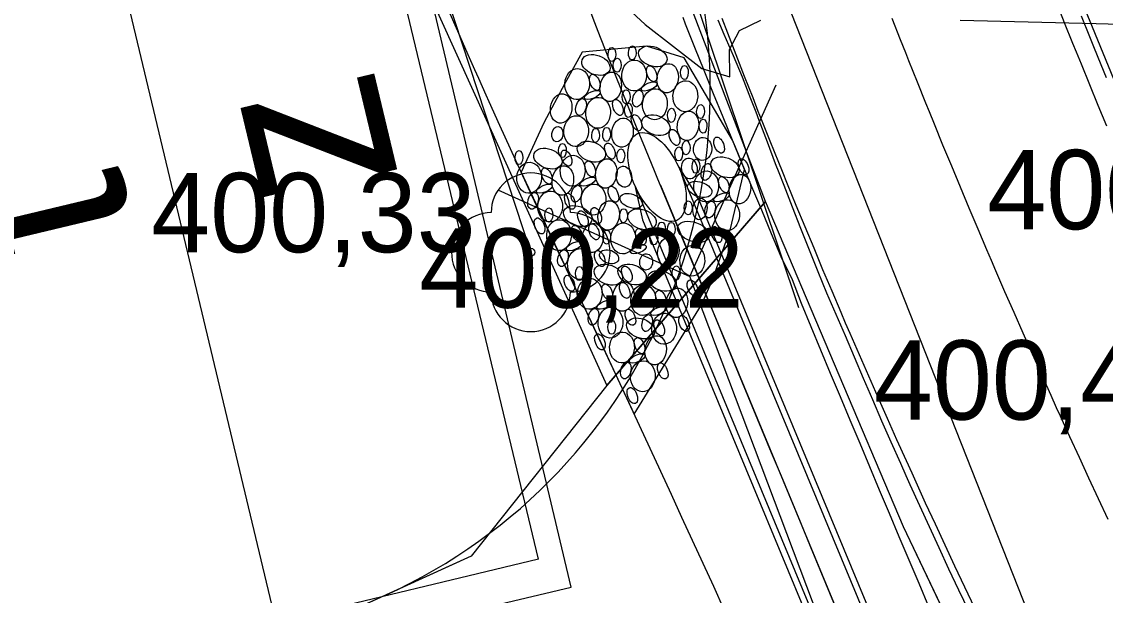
# Model space of a CAD drawing. Extents: x -574342 to -507939, y -1144044 to -1123894.
# Drawn here: x -508545.62 to -508531.96, y -1143255.8 to -1143248.56 of the extents above; entities that cross this region are included whole.
import ezdxf

# ---------------------------------------------------------------- set-up
doc = ezdxf.new("R2010")
doc.units = 0
for name, color, linetype in [('01_PARCELY_NAVRH_PC', 7, 'Continuous'), ('01_PARCELY_NAVRH_VHO', 7, 'Continuous'), ('01_PARCELY_NAVRH_ŽP', 7, 'Continuous'), ('04_ZPF_TECH_OPATŘEN_STAV', 7, 'Continuous'), ('1000', 7, 'Continuous'), ('21', 7, 'Continuous'), ('37', 7, 'Continuous'), ('54', 7, 'Continuous'), ('55', 7, 'Continuous'), ('62', 7, 'Continuous'), ('cesty', 7, 'Continuous'), ('Level 255', 7, 'Continuous'), ('propustek', 7, 'Continuous'), ('SO 101_popis oblouku', 7, 'Continuous'), ('VRST HL', 7, 'Continuous')]:
    doc.layers.add(name, color=color, linetype=linetype)

msp = doc.modelspace()

# ---------------------------------------------------------------- linework, layer by layer
msp.add_lwpolyline([(-508538.692, -1143255.691), (-508544.119, -1143232.805), (-508565.304, -1143237.829), (-508559.878, -1143260.714)], close=True)
at = {"layer": '01_PARCELY_NAVRH_PC'}
for points in [[(-508524.61, -1143277.77), (-508531.94, -1143260.32), (-508534.5, -1143254.93), (-508536.24, -1143250.83), (-508539.07, -1143243.44), (-508539.77, -1143241.25), (-508540.55, -1143238.43), (-508542.83, -1143228.38), (-508544.32, -1143217.47), (-508545.45, -1143205.07), (-508545.52, -1143198.58), (-508545.24, -1143191.32), (-508544.97, -1143188.3), (-508544.25, -1143181.83), (-508541.94, -1143173.53), (-508537.18, -1143176.51), (-508538.65, -1143182.46), (-508540.32, -1143193.28), (-508540.02, -1143209.35), (-508538.46, -1143221.35), (-508537.02, -1143231.11), (-508535.34, -1143238.37), (-508531.16, -1143250.06), (-508524.26, -1143263.08)], [(-508524.61, -1143277.77), (-508531.94, -1143260.32), (-508534.5, -1143254.93), (-508536.24, -1143250.83), (-508539.07, -1143243.44), (-508539.77, -1143241.25), (-508540.55, -1143238.43), (-508542.83, -1143228.38), (-508544.32, -1143217.47), (-508545.45, -1143205.07), (-508545.52, -1143198.58), (-508545.24, -1143191.32), (-508544.97, -1143188.3), (-508544.25, -1143181.83), (-508541.94, -1143173.53), (-508537.18, -1143176.51), (-508538.65, -1143182.46), (-508540.32, -1143193.28), (-508540.02, -1143209.35), (-508538.46, -1143221.35), (-508537.02, -1143231.11), (-508535.34, -1143238.37), (-508531.16, -1143250.06), (-508524.26, -1143263.08)], [(-508866.763, -1143529.283), (-508859.41, -1143516.97), (-508810.66, -1143431.99), (-508773.29, -1143386.75), (-508766.4, -1143380.31), (-508664.99, -1143316.89), (-508539, -1143259.35), (-508535.36, -1143259.89), (-508531.94, -1143260.32), (-508534.5, -1143254.93), (-508536.24, -1143250.83), (-508538.24, -1143253.15), (-508539.95, -1143255.3), (-508667.19, -1143313.15), (-508770.98, -1143377.64), (-508813.09, -1143427.79), (-508861.39, -1143510.97), (-508866.763, -1143520.059)]]:
    msp.add_lwpolyline(points, dxfattribs=at)
at = {"layer": '01_PARCELY_NAVRH_VHO'}
msp.add_lwpolyline([(-508536.24, -1143250.83), (-508539.07, -1143243.44), (-508539.77, -1143241.25), (-508540.55, -1143238.43), (-508542.83, -1143228.38), (-508544.32, -1143217.47), (-508545.45, -1143205.07), (-508545.52, -1143198.58), (-508545.24, -1143191.32), (-508544.97, -1143188.3), (-508544.25, -1143181.83), (-508551.68, -1143170.14), (-508558.5, -1143170.32), (-508555.03, -1143173.64), (-508548.66, -1143186.8), (-508549.63, -1143198.15), (-508549.79, -1143203.71), (-508547.53, -1143223.9), (-508542.99, -1143242.68), (-508538.24, -1143253.15)], close=True, dxfattribs=at)
at = {"layer": '01_PARCELY_NAVRH_ŽP'}
msp.add_lwpolyline([(-508555.03, -1143173.64), (-508548.66, -1143186.8), (-508549.63, -1143198.15), (-508549.79, -1143203.71), (-508547.53, -1143223.9), (-508542.99, -1143242.68), (-508538.24, -1143253.15), (-508539.95, -1143255.3), (-508547.25, -1143258.62), (-508651.11, -1143191.46), (-508662.59, -1143152.85), (-508637.59, -1143153.08), (-508621.09, -1143158.13), (-508610.87, -1143164.96), (-508585.59, -1143176.01), (-508569.25, -1143175.97)], close=True, dxfattribs=at)
at = {"layer": '04_ZPF_TECH_OPATŘEN_STAV'}
for points in [[(-508539.614, -1143250.685), (-508537.197, -1143251.776), (-508536.106, -1143249.359)], [(-508534.989, -1143257.623), (-508537.197, -1143251.776)]]:
    msp.add_lwpolyline(points, dxfattribs=at)
at = {"layer": '1000'}
for points in [[(-508532.579, -1143248.315), (-508532.475, -1143248.575), (-508532.37, -1143248.836), (-508532.326, -1143248.943), (-508532.264, -1143249.096), (-508532.158, -1143249.356), (-508532.051, -1143249.615), (-508531.943, -1143249.875)], [(-508536.762, -1143255.976), (-508536.894, -1143255.685), (-508537.027, -1143255.395), (-508537.16, -1143255.105), (-508537.294, -1143254.814), (-508537.427, -1143254.524), (-508537.561, -1143254.234), (-508537.695, -1143253.945), (-508537.83, -1143253.655), (-508537.964, -1143253.365), (-508538.099, -1143253.075), (-508538.234, -1143252.786), (-508538.369, -1143252.496), (-508538.504, -1143252.207), (-508538.64, -1143251.918), (-508538.776, -1143251.629), (-508538.912, -1143251.34), (-508539.008, -1143251.136), (-508539.048, -1143251.049), (-508539.185, -1143250.755), (-508539.321, -1143250.461), (-508539.457, -1143250.166), (-508539.591, -1143249.871), (-508539.724, -1143249.575), (-508539.762, -1143249.492), (-508539.857, -1143249.278), (-508539.906, -1143249.169), (-508539.989, -1143248.982), (-508540.12, -1143248.685), (-508540.25, -1143248.387)], [(-508532.264, -1143248.491), (-508532.158, -1143248.75), (-508532.115, -1143248.857), (-508532.052, -1143249.01), (-508531.946, -1143249.269)], [(-508534.181, -1143255.94), (-508534.306, -1143255.646), (-508534.43, -1143255.353), (-508534.555, -1143255.059), (-508534.679, -1143254.765), (-508534.803, -1143254.471), (-508534.927, -1143254.177), (-508535.05, -1143253.882), (-508535.174, -1143253.588), (-508535.297, -1143253.294), (-508535.42, -1143252.999), (-508535.543, -1143252.705), (-508535.665, -1143252.41), (-508535.787, -1143252.115), (-508535.902, -1143251.817), (-508536.043, -1143251.53), (-508536.166, -1143251.236), (-508536.289, -1143250.941), (-508536.412, -1143250.647), (-508536.534, -1143250.352), (-508536.621, -1143250.144), (-508536.656, -1143250.058), (-508536.776, -1143249.766), (-508536.895, -1143249.474), (-508537.014, -1143249.181), (-508537.131, -1143248.888), (-508537.248, -1143248.595), (-508537.28, -1143248.512)], [(-508536.843, -1143248.54), (-508536.766, -1143248.721), (-508536.651, -1143248.99), (-508536.535, -1143249.259), (-508536.43, -1143249.532), (-508536.364, -1143249.702), (-508536.326, -1143249.805), (-508536.222, -1143250.078), (-508536.118, -1143250.351), (-508536.074, -1143250.464), (-508536.012, -1143250.624), (-508535.906, -1143250.896), (-508535.799, -1143251.168), (-508535.691, -1143251.44), (-508535.583, -1143251.712), (-508535.474, -1143251.983), (-508535.355, -1143252.251), (-508535.296, -1143252.384), (-508535.239, -1143252.519), (-508535.125, -1143252.788), (-508535.01, -1143253.057), (-508534.894, -1143253.326), (-508534.777, -1143253.594), (-508534.66, -1143253.862), (-508534.541, -1143254.129), (-508534.472, -1143254.285), (-508534.422, -1143254.396), (-508534.302, -1143254.663), (-508534.18, -1143254.929), (-508534.057, -1143255.194), (-508533.934, -1143255.459), (-508533.809, -1143255.724), (-508533.684, -1143255.988)], [(-508536.792, -1143248.52), (-508536.722, -1143248.704), (-508536.616, -1143248.977), (-508536.51, -1143249.249), (-508536.403, -1143249.521), (-508536.336, -1143249.691), (-508536.296, -1143249.793), (-508536.187, -1143250.064), (-508536.078, -1143250.335), (-508536.033, -1143250.447), (-508535.968, -1143250.606), (-508535.858, -1143250.877), (-508535.746, -1143251.147), (-508535.634, -1143251.416), (-508535.521, -1143251.686), (-508535.407, -1143251.955), (-508535.292, -1143252.224), (-508535.235, -1143252.358), (-508535.177, -1143252.492), (-508535.061, -1143252.761), (-508534.944, -1143253.028), (-508534.826, -1143253.296), (-508534.708, -1143253.563), (-508534.589, -1143253.83), (-508534.469, -1143254.096), (-508534.398, -1143254.252), (-508534.348, -1143254.363), (-508534.227, -1143254.628), (-508534.104, -1143254.894), (-508533.981, -1143255.159), (-508533.858, -1143255.424), (-508533.733, -1143255.688), (-508533.608, -1143255.952)]]:
    msp.add_lwpolyline(points, dxfattribs=at)
at = {"layer": '21'}
for points in [[(-508535.307, -1143256.062), (-508535.429, -1143255.768), (-508535.552, -1143255.473), (-508535.674, -1143255.178), (-508535.796, -1143254.883), (-508535.919, -1143254.589), (-508536.041, -1143254.294), (-508536.164, -1143253.999), (-508536.286, -1143253.705), (-508536.409, -1143253.41), (-508536.531, -1143253.115), (-508536.653, -1143252.821), (-508536.776, -1143252.526), (-508536.898, -1143252.231), (-508537.021, -1143251.936), (-508537.143, -1143251.642), (-508537.266, -1143251.347), (-508537.388, -1143251.052), (-508537.511, -1143250.758), (-508537.597, -1143250.55), (-508537.633, -1143250.463), (-508537.755, -1143250.168), (-508537.875, -1143249.873), (-508537.995, -1143249.577), (-508538.114, -1143249.281), (-508538.232, -1143248.984), (-508538.265, -1143248.901), (-508538.349, -1143248.687), (-508538.392, -1143248.577), (-508538.465, -1143248.39)], [(-508534.648, -1143248.521), (-508534.543, -1143248.787), (-508534.477, -1143248.954), (-508534.437, -1143249.054), (-508534.331, -1143249.32), (-508534.224, -1143249.586), (-508534.18, -1143249.695), (-508534.116, -1143249.851), (-508534.008, -1143250.116), (-508533.898, -1143250.381), (-508533.788, -1143250.646), (-508533.678, -1143250.91), (-508533.566, -1143251.174), (-508533.454, -1143251.437), (-508533.397, -1143251.568), (-508533.341, -1143251.7), (-508533.227, -1143251.963), (-508533.112, -1143252.226), (-508532.997, -1143252.488), (-508532.881, -1143252.75), (-508532.764, -1143253.012), (-508532.646, -1143253.273), (-508532.577, -1143253.426), (-508532.528, -1143253.534), (-508532.409, -1143253.794), (-508532.289, -1143254.055), (-508532.168, -1143254.315), (-508532.047, -1143254.574), (-508531.925, -1143254.833)]]:
    msp.add_lwpolyline(points, dxfattribs=at)
at = {"layer": '37'}
for points in [[(-508544.44, -1143182.59), (-508545.29, -1143193.14), (-508544.8, -1143205.6), (-508541.6, -1143228.19), (-508538.07, -1143243), (-508531.89, -1143258.66), (-508522.3, -1143275.29), (-508518.1, -1143283.75), (-508512.73, -1143299.25), (-508510.49, -1143313.12)], [(-508544.44, -1143182.59), (-508545.29, -1143193.14), (-508544.8, -1143205.6), (-508541.6, -1143228.19), (-508538.07, -1143243), (-508531.89, -1143258.66), (-508522.3, -1143275.29), (-508518.1, -1143283.75), (-508512.73, -1143299.25), (-508510.49, -1143313.12)], [(-508507.09, -1143312.37), (-508509.64, -1143298.16), (-508515.1, -1143282.44), (-508519.8, -1143273.76), (-508526.92, -1143261.04), (-508530.09, -1143253.58), (-508534.91, -1143241.83), (-508538.52, -1143226.92), (-508541.3, -1143204.98), (-508541.88, -1143193.39), (-508540.68, -1143183.59)], [(-508507.09, -1143312.37), (-508509.64, -1143298.16), (-508515.1, -1143282.44), (-508519.8, -1143273.76), (-508526.92, -1143261.04), (-508530.09, -1143253.58), (-508534.91, -1143241.83), (-508538.52, -1143226.92), (-508541.3, -1143204.98), (-508541.88, -1143193.39), (-508540.68, -1143183.59)]]:
    msp.add_lwpolyline(points, dxfattribs=at)
at = {"layer": '54'}
msp.add_circle((-508539.2, -1143251.47), 0.05, dxfattribs=at)
for centre, start, end in [((-508539.2, -1143250.97), 0, 180), ((-508539.7, -1143251.47), 90, 270), ((-508538.7, -1143251.47), 270, 90), ((-508539.2, -1143251.97), 180, 0)]:
    msp.add_arc(centre, 0.5, start, end, dxfattribs=at)
at = {"layer": '55'}
msp.add_line((-508539.2, -1143251.47), (-508547.83, -1143225.16), dxfattribs=at)
msp.add_line((-508539.2, -1143251.47), (-508547.83, -1143225.16), dxfattribs=at)
at = {"layer": '62'}
msp.add_lwpolyline([(-508535.82, -1143252.17), (-508543.49, -1143229.3), (-508544.91, -1143218.28), (-508546.55, -1143206.05), (-508547.23, -1143192.43), (-508546.71, -1143185.69)], dxfattribs=at)
msp.add_lwpolyline([(-508535.82, -1143252.17), (-508543.49, -1143229.3), (-508544.91, -1143218.28), (-508546.55, -1143206.05), (-508547.23, -1143192.43), (-508546.71, -1143185.69)], dxfattribs=at)
at = {"layer": 'cesty'}
msp.add_arc((-508543.938, -1143249.426), 7, 294.5203, 21.1483, dxfattribs=at)
at = {"layer": 'propustek'}
for p, q in [((-508537.335, -1143250.399), (-508537.097, -1143250.771)), ((-508537.335, -1143250.399), (-508533.084, -1143260.63)), ((-508537.889, -1143250.629), (-508537.793, -1143251.06)), ((-508537.882, -1143250.646), (-508533.651, -1143260.831)), ((-508537.566, -1143250.623), (-508533.141, -1143261.276)), ((-508537.103, -1143250.761), (-508533.181, -1143260.194)), ((-508537.793, -1143251.06), (-508533.888, -1143260.46))]:
    msp.add_line(p, q, dxfattribs=at)
msp.add_lwpolyline([(-508539.037, -1143249.838), (-508539.321, -1143250.461), (-508538.776, -1143251.629), (-508538.437, -1143252.352), (-508537.896, -1143253.512), (-508537.046, -1143252.132), (-508536.909, -1143251.818), (-508536.683, -1143251.175), (-508536.504, -1143250.425), (-508536.656, -1143250.058), (-508537.265, -1143249.018), (-508537.74, -1143248.872), (-508538.553, -1143248.946), (-508538.772, -1143249.341)], close=True, dxfattribs=at)
for centre, major_axis, ratio in [((-508538.177, -1143248.977), (-0.0019, -0.0885), 0.557809), ((-508537.921, -1143248.958), (-0.0019, -0.0885), 0.557809), ((-508537.662, -1143249.001), (0.174, -0.065), 0.657512), ((-508538.379, -1143249.109), (0.174, -0.065), 0.657512), ((-508538.111, -1143249.112), (-0.0019, -0.0885), 0.557809), ((-508537.898, -1143249.242), (-0.011, -0.195), 0.799162), ((-508538.616, -1143249.35), (-0.011, -0.195), 0.799162), ((-508537.676, -1143249.22), (0.0411, -0.0988), 0.545699), ((-508537.474, -1143249.277), (-0.026, -0.184), 0.724539), ((-508537.264, -1143249.205), (-0.0019, -0.0885), 0.557809), ((-508538.393, -1143249.328), (0.0411, -0.0988), 0.545699), ((-508538.192, -1143249.385), (-0.026, -0.184), 0.724539), ((-508537.707, -1143249.38), (0.0988, 0.0411), 0.409091), ((-508537.252, -1143249.503), (-0.011, -0.195), 0.799162), ((-508538.424, -1143249.488), (0.0988, 0.0411), 0.409091), ((-508537.998, -1143249.511), (-0.0019, -0.0885), 0.557809), ((-508537.85, -1143249.533), (-0.03, -0.105), 0.579616), ((-508537.635, -1143249.605), (-0.011, -0.195), 0.799162), ((-508538.817, -1143249.657), (-0.026, -0.184), 0.724539), ((-508538.567, -1143249.64), (-0.03, -0.105), 0.579616), ((-508538.352, -1143249.713), (-0.011, -0.195), 0.799162), ((-508538.102, -1143249.645), (0.0411, -0.0988), 0.545699), ((-508537.97, -1143249.681), (-0.0019, -0.0885), 0.557809), ((-508537.866, -1143249.837), (0.0411, -0.0988), 0.545699), ((-508537.624, -1143249.869), (0.174, -0.065), 0.657512), ((-508537.427, -1143249.744), (-0.0019, -0.0885), 0.557809), ((-508537.219, -1143249.877), (-0.026, -0.184), 0.724539), ((-508537.06, -1143249.696), (-0.0019, -0.0885), 0.557809), ((-508538.628, -1143249.944), (-0.011, -0.195), 0.799162), ((-508538.044, -1143249.962), (-0.026, -0.184), 0.724539), ((-508537.029, -1143249.881), (-0.0019, -0.0885), 0.557809), ((-508538.865, -1143249.982), (-0.0134, -0.0962), 0.724539), ((-508538.383, -1143249.997), (-0.0019, -0.0885), 0.557809), ((-508538.244, -1143249.985), (-0.0019, -0.0885), 0.557809), ((-508537.608, -1143250.522), (0.247, -0.547), 0.499987), ((-508537.388, -1143250.023), (0.0411, -0.0988), 0.545699), ((-508538.802, -1143250.188), (-0.0019, -0.0885), 0.557809), ((-508538.436, -1143250.202), (0.174, -0.065), 0.657512), ((-508538.202, -1143250.195), (0.0411, -0.0988), 0.545699), ((-508537.242, -1143250.152), (-0.0019, -0.0885), 0.557809), ((-508537.034, -1143250.168), (-0.008, -0.144), 0.799162), ((-508536.826, -1143250.12), (0.0411, -0.0988), 0.545699), ((-508539.349, -1143250.277), (-0.0019, -0.0885), 0.557809), ((-508538.984, -1143250.29), (0.174, -0.065), 0.657512), ((-508538.672, -1143250.443), (-0.011, -0.195), 0.799162), ((-508538.75, -1143250.284), (0.0411, -0.0988), 0.545699), ((-508538.066, -1143250.255), (-0.0019, -0.0885), 0.557809), ((-508537.335, -1143250.231), (-0.0019, -0.0885), 0.557809), ((-508536.752, -1143250.399), (0.174, -0.065), 0.657512), ((-508539.22, -1143250.531), (-0.011, -0.195), 0.799162), ((-508538.997, -1143250.509), (0.0411, -0.0988), 0.545699), ((-508538.796, -1143250.566), (-0.026, -0.184), 0.724539), ((-508538.45, -1143250.42), (0.0411, -0.0988), 0.545699), ((-508538.248, -1143250.477), (-0.026, -0.184), 0.724539), ((-508538.026, -1143250.517), (0.02, -0.131), 0.73939), ((-508537.201, -1143250.414), (0.02, -0.131), 0.73939), ((-508537.118, -1143250.386), (-0.0019, -0.0885), 0.557809), ((-508536.986, -1143250.458), (-0.03, -0.105), 0.579616), ((-508536.518, -1143250.393), (0.0411, -0.0988), 0.545699), ((-508538.481, -1143250.581), (0.0988, 0.0411), 0.409091), ((-508536.988, -1143250.64), (-0.011, -0.195), 0.799162), ((-508536.766, -1143250.618), (0.0411, -0.0988), 0.545699), ((-508536.564, -1143250.675), (-0.026, -0.184), 0.724539), ((-508539.029, -1143250.669), (0.0988, 0.0411), 0.409091), ((-508538.624, -1143250.733), (-0.03, -0.105), 0.579616), ((-508538.409, -1143250.806), (-0.011, -0.195), 0.799162), ((-508538.159, -1143250.738), (0.0411, -0.0988), 0.545699), ((-508537.07, -1143250.678), (-0.15, 0.053), 0.586676), ((-508539.171, -1143250.822), (-0.03, -0.105), 0.579616), ((-508538.956, -1143250.894), (-0.011, -0.195), 0.799162), ((-508538.707, -1143250.827), (0.0411, -0.0988), 0.545699), ((-508538.219, -1143251.006), (-0.026, -0.184), 0.724539), ((-508537.934, -1143250.823), (-0.138, 0.049), 0.586676), ((-508537.068, -1143250.925), (-0.014, -0.135), 0.657512), ((-508536.939, -1143250.931), (-0.03, -0.105), 0.579616), ((-508536.797, -1143250.778), (0.0988, 0.0411), 0.409091), ((-508536.724, -1143251.003), (-0.011, -0.195), 0.799162), ((-508538.973, -1143251), (-0.0019, -0.0885), 0.557809), ((-508538.608, -1143251.014), (0.174, -0.065), 0.657512), ((-508538.542, -1143251.049), (0.0411, -0.0988), 0.545699), ((-508538.374, -1143251.007), (0.0411, -0.0988), 0.545699), ((-508538.03, -1143251.01), (-0.0019, -0.0885), 0.557809), ((-508537.798, -1143251.055), (0.174, -0.065), 0.657512), ((-508537.216, -1143250.911), (-0.0019, -0.0885), 0.557809), ((-508539.089, -1143251.138), (0.0411, -0.0988), 0.545699), ((-508538.844, -1143251.255), (-0.011, -0.195), 0.799162), ((-508537.551, -1143251.178), (-0.0019, -0.0885), 0.557809), ((-508537.15, -1143251.213), (-0.195, 0.069), 0.586676), ((-508538.621, -1143251.233), (0.0411, -0.0988), 0.545699), ((-508538.42, -1143251.29), (-0.026, -0.184), 0.724539), ((-508538.402, -1143251.212), (0.0411, -0.0988), 0.545699), ((-508538.243, -1143251.28), (-0.0019, -0.0885), 0.557809), ((-508538.035, -1143251.296), (-0.011, -0.195), 0.799162), ((-508537.812, -1143251.274), (0.0411, -0.0988), 0.545699), ((-508537.649, -1143251.29), (-0.0019, -0.0885), 0.557809), ((-508537.429, -1143251.182), (-0.0019, -0.0885), 0.557809), ((-508536.858, -1143251.247), (0.0411, -0.0988), 0.545699), ((-508538.653, -1143251.393), (0.0988, 0.0411), 0.409091), ((-508537.466, -1143251.464), (-0.026, -0.184), 0.724539), ((-508538.795, -1143251.545), (-0.03, -0.105), 0.579616), ((-508538.58, -1143251.618), (-0.011, -0.195), 0.799162), ((-508538.331, -1143251.55), (0.0411, -0.0988), 0.545699), ((-508538.213, -1143251.527), (0.117, -0.043), 0.657512), ((-508537.843, -1143251.434), (0.0988, 0.0411), 0.409091), ((-508537.746, -1143251.592), (0.006, 0.102), 0.799162), ((-508537.164, -1143251.576), (-0.011, -0.195), 0.799162), ((-508538.222, -1143251.753), (0.174, -0.065), 0.657512), ((-508537.923, -1143251.75), (0.174, -0.065), 0.657512), ((-508537.988, -1143251.746), (0.0411, -0.0988), 0.545699), ((-508538.713, -1143251.861), (0.0411, -0.0988), 0.545699), ((-508538.588, -1143251.739), (-0.0019, -0.0885), 0.557809), ((-508537.545, -1143251.831), (0.174, -0.065), 0.657512), ((-508537.367, -1143251.73), (-0.0019, -0.0885), 0.557809), ((-508538.458, -1143251.994), (-0.011, -0.195), 0.799162), ((-508538.236, -1143251.971), (0.0411, -0.0988), 0.545699), ((-508538.034, -1143252.028), (-0.026, -0.184), 0.724539), ((-508538.016, -1143251.951), (0.0411, -0.0988), 0.545699), ((-508537.782, -1143252.072), (-0.011, -0.195), 0.799162), ((-508537.358, -1143252.107), (-0.026, -0.184), 0.724539), ((-508537.162, -1143251.919), (0.0411, -0.0988), 0.545699), ((-508537.559, -1143252.05), (0.0411, -0.0988), 0.545699), ((-508538.41, -1143252.284), (-0.03, -0.105), 0.579616), ((-508538.267, -1143252.132), (0.0988, 0.0411), 0.409091), ((-508538.195, -1143252.357), (-0.011, -0.195), 0.799162), ((-508537.945, -1143252.289), (0.0411, -0.0988), 0.545699), ((-508537.59, -1143252.21), (0.0988, 0.0411), 0.409091), ((-508537.814, -1143252.43), (0.174, -0.065), 0.657512), ((-508537.733, -1143252.363), (-0.03, -0.105), 0.579616), ((-508537.518, -1143252.435), (-0.011, -0.195), 0.799162), ((-508537.58, -1143252.423), (0.0411, -0.0988), 0.545699), ((-508537.268, -1143252.368), (0.0411, -0.0988), 0.545699), ((-508538.18, -1143252.416), (-0.0019, -0.0885), 0.557809), ((-508538.328, -1143252.6), (0.0411, -0.0988), 0.545699), ((-508538.05, -1143252.671), (-0.011, -0.195), 0.799162), ((-508537.828, -1143252.648), (0.0411, -0.0988), 0.545699), ((-508537.626, -1143252.706), (-0.026, -0.184), 0.724539), ((-508538.002, -1143252.961), (-0.03, -0.105), 0.579616), ((-508537.859, -1143252.809), (0.0988, 0.0411), 0.409091), ((-508537.787, -1143253.034), (-0.011, -0.195), 0.799162), ((-508537.537, -1143252.966), (0.0411, -0.0988), 0.545699), ((-508537.92, -1143253.277), (0.0411, -0.0988), 0.545699)]:
    msp.add_ellipse(centre, major_axis=major_axis, ratio=ratio, dxfattribs=at)
at = {"layer": 'SO 101_popis oblouku'}
for p, q in [((-508539.103, -1143255.341), (-508544.379, -1143233.297)), ((-508542.409, -1143256.132), (-508547.685, -1143234.088)), ((-508539.103, -1143255.341), (-508555.636, -1143259.298))]:
    msp.add_line(p, q, dxfattribs=at)
at = {"layer": 'VRST HL'}
for points in [[(-508538.839, -1143247.596), (-508537.76, -1143248.599), (-508537.043, -1143249.153), (-508536.689, -1143249.258), (-508536.696, -1143248.913), (-508536.567, -1143248.675), (-508536.302, -1143248.545)], [(-508533.786, -1143248.544), (-508532.075, -1143248.587), (-508530.874, -1143248.619)]]:
    msp.add_lwpolyline(points, dxfattribs=at)

# ---------------------------------------------------------------- texts
at = {"layer": 'Level 255'}
for s, p in [('400,15', (-508533.445, -1143251.18)), ('400,33', (-508543.985, -1143251.47)), ('400,22', (-508540.605, -1143252.17)), ('400,45', (-508534.875, -1143253.58))]:
    msp.add_text(s, height=1, dxfattribs=at).set_placement(p)
at = {"layer": 'SO 101_popis oblouku'}
for s, p in [('z', (-508540.856, -1143250.544)), ('t', (-508544.2, -1143251.178))]:
    msp.add_text(s, height=2.267, rotation=103.4546, dxfattribs=at).set_placement(p)

doc.saveas('drawing.dxf')
